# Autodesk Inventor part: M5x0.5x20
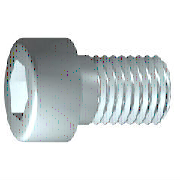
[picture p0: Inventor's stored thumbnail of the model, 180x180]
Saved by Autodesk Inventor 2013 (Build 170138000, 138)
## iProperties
IsCustomPart: 0
Company: 한국ATC센터
Created: 2009-02
Part Number: M5x0.5x20
Material: Steel, Mild
Description: 6각머리 태핑 나사
Document SubType Name: Modeling
Standard: KS B 1003
Designer: KYOUNG IL JANG
Standards Organization: KS
Language: ko-KR
Size Designation: M 5 x 20
Categories: <MemberInstance><Categories><Category DisplayName="조임쇠" InternalName="e4da775c-781d-43d5-af7c-5136215cf5a6" Mnemonic="FSTN"><Category DisplayName="볼트" InternalN
Density: 7.86 g/cm^3
Mass: 4.9629 g
Surface Area: 5.88238 cm^2
Volume: 0.631412 cm^3
Author: KYOUNG IL JANG
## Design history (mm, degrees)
sketch "스케치1"
  geometry: L1 (-1.167, 0)-(20, 0); L2 (20, 0)-(20, 2.5); L3 (20, 2.5)-(2, 2.5); L4 (2, 2.5)-(1.509, 2.5); L5 (1.509, 2.5)-(0, 2.5); L6 (0, 2.5)-(0, 4.25); L7 (0, 4.25)-(-5, 4.25); L8 (-5, 4.25)-(-5, 2.309); L9 (-5, 2.309)-(-2.5, 2.309); L10 (-2.5, 2.309)-(-1.167, 0); L11 (-10, 0)-(25, 0) reference; L12 (0, -0.85)-(0, 5.1) reference; L13 (2, 2.5)-(0, 2.5)
  constraints: 22 end point, 6 parallel, 2 collinear, 2 perpendicular, 1 horizontal, 1 point on line
  dimensions: "d1" = 18 distance from line of L3.end L2 (= GEL); "d2" = 0.49086 distance of L4.end L3.end (computed from GAL); "d3" = 5 distance between parallel lines of L8 L6 (= KOH); "d4" = 2.5 distance of L8.end L9.end (= INTI); "d5" = 60 deg angle of L10 L1; "d6" = 5 diameter of L3 L1 (= GD); "d7" = 5 diameter of L5 L1 (= BDM); "d8" = 4.6188 diameter of L9 L1 (= 1.1547 x SW); "d9" = 8.5 diameter of L7 L1 (= KOD); "d26" = 20 distance between parallel lines of L12 L2 (= NLG)
revolve "본체" sketch "스케치1" stored, may be unused: angle "d10" = 90 deg
sketch "스케치2"
  geometry: L1 (0, -5.95)-(0, 5.95) reference; L2 (-5.95, 0)-(5.95, 0) reference; L3 (2.309, 0)-(1.155, -2); L4 (1.155, -2)-(-1.155, -2); L5 (-1.155, -2)-(-2.309, 0); L6 (-2.309, 0)-(-1.155, 2); L7 (-1.155, 2)-(1.155, 2); L8 (1.155, 2)-(2.309, 0); 2 further points
  constraints: 12 end point, 1 coincident, 1 horizontal alignment, 1 point on line, 12 other
extrude "슬롯" join sketch "스케치2" stored distance "d11" = 10; taper "d12" = 0 deg
workplane "Work Plane1"
fillet "Fillet2" dims "d30" = 0.1 (= R)
body "Solid1"
fillet "모깎기1" dims "d17" = 0.5 (= RR)
feature "스레드" dims "d13" = 18 (= GEL), "d14" = 0
chamfer "모따기1" distance "d15" = 0.49076 (= -0.5 x SPD + 0.5 x GD); stored, may be unused: second distance "d16" = 0.49076 (= GUL), angle "d27" = 45 deg
other parameters: "GD" = 5 (= NND) [user parameter; used in 2 equation terms], "NLG" = 20 [user parameter; used in 1 equation term], "GEL" = 18 [user parameter; used in 2 equation terms], "KOD" = 8.5 [user parameter; used in 1 equation term], "KOH" = 5 [user parameter; used in 1 equation term], "INTI" = 2.5 [user parameter; used in 1 equation term], "GAL" = 0.49076 (= 0.61345 x PTC) [user parameter; used in 1 equation term], "GUL" = 0.49076 (= 0.61345 x PTC) [user parameter; used in 1 equation term], "BDM" = 5 (= NND) [user parameter; used in 1 equation term], "SW" = 4 [user parameter; used in 2 equation terms], "RR" = 0.5 [user parameter; used in 1 equation term], "SPD" = 4.01848 (= NND - 1.2269 x PTC) [user parameter; used in 1 equation term], "d19" = 0, "d28" = 0, "d29" = 0, "R" = 0.1 [user parameter; used in 1 equation term], "PHH" = 0.2 [user parameter], "GD1" = 4.01848 (= THREADDIA - 1.2269 x PTC) [user parameter], "THREADDIA" = 5 [user parameter; used in 1 equation term], "FAWI" = 45 deg [user parameter], "TPU" = 12.5 (computed from PTC) [user parameter], "PTC" = 0.8 [user parameter; used in 5 equation terms], "NND" = 5 [user parameter; used in 3 equation terms], "TOA" = 30 deg [user parameter], "E0" = 4.62 (= 1.155 x SW) [user parameter]
